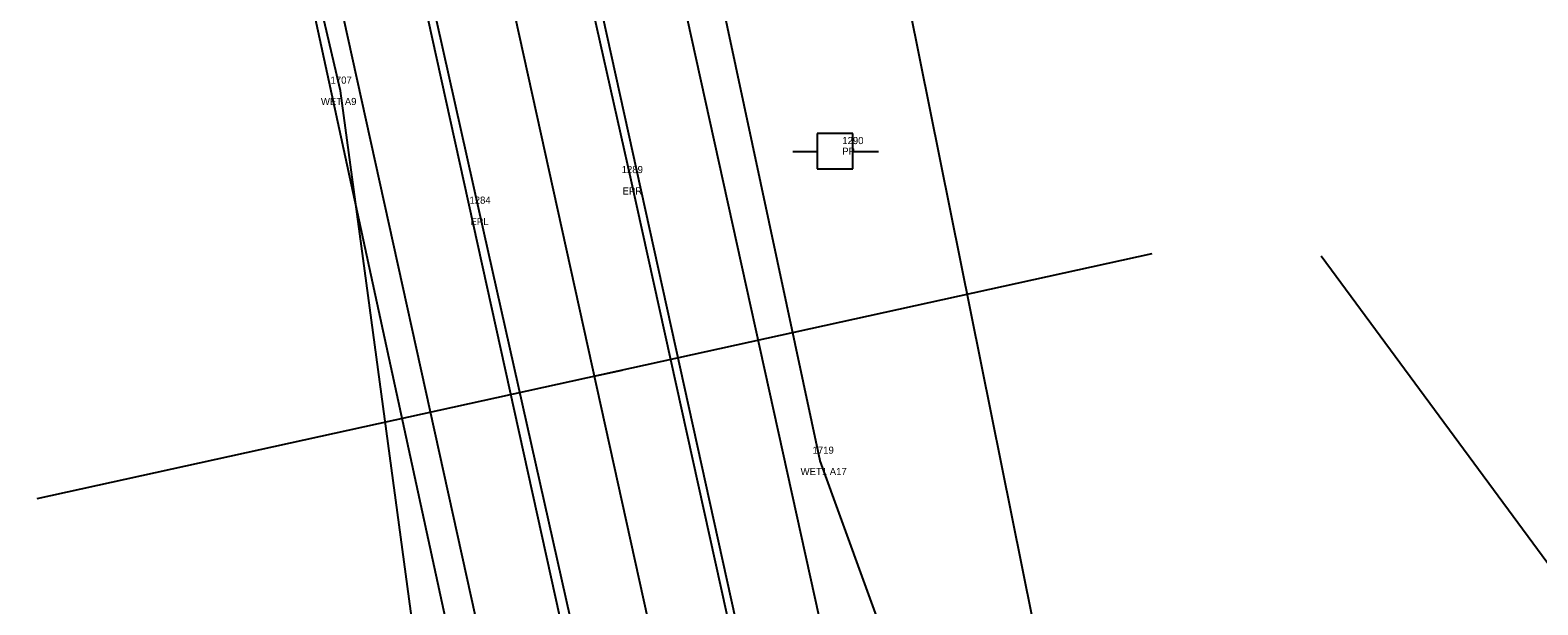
# Model space of a CAD drawing. Extents: x 2522090 to 2524658, y 882711 to 887512.
# Drawn here: x 2523667.1 to 2523878.4, y 885285.4 to 885366 of the extents above; entities that cross this region are included whole.
import ezdxf

# ---------------------------------------------------------------- set-up
doc = ezdxf.new("R2010")
doc.units = 0
for name, color, linetype in [('RD_EV_JurisArea', 7, 'Continuous'), ('RD_EX_H2O_WetLd_txCode', 7, 'Continuous'), ('RD_EX_Road', 7, 'Continuous'), ('RD_EX_Road_txCode', 7, 'Continuous'), ('RD_EX_UT', 7, 'Continuous'), ('RD_EX_UT_txCode', 7, 'Continuous'), ('RD_EX_VEG', 7, 'Continuous'), ('RD_HC_Cl', 7, 'Continuous'), ('RD_HC_Data_Tic', 7, 'Continuous'), ('RD_PD_Final_TrvlWay', 7, 'Continuous'), ('RD_PD_GR', 7, 'Continuous'), ('RD_PD_PatLn5', 7, 'Continuous'), ('RD_PD_PatLn6', 7, 'Continuous'), ('RD_SMD_Locator', 7, 'Continuous')]:
    doc.layers.add(name, color=color, linetype=linetype)

msp = doc.modelspace()

# ---------------------------------------------------------------- linework, layer by layer
at = {"layer": 'RD_EV_JurisArea'}
for points in [[(2523761.17, 885134.03), (2523740.58, 885149.03), (2523730.55, 885209.77), (2523710.6, 885357.47), (2523698.09, 885411.19), (2523674.93, 885498.62), (2523657.6, 885564.24), (2523640.82, 885610.87), (2523583.66, 885726.91), (2523539.21, 885693.17), (2523494.42, 885646.98)], [(2523761.17, 885134.03), (2523808.21, 885149.21), (2523821.91, 885178.64), (2523802.85, 885236.55), (2523777.81, 885305.56), (2523748.2, 885444.32), (2523730.68, 885516.88), (2523708.64, 885617.3), (2523698.71, 885662.02), (2523727.83, 885665.82), (2523757.3, 885671.75)]]:
    msp.add_lwpolyline(points, dxfattribs=at)
at = {"layer": 'RD_EX_Road'}
for p, q in [((2523751.35, 885344.92), (2523730.54, 885437.51)), ((2523730.02, 885340.63), (2523709.49, 885433.05)), ((2523771.24, 885254.79), (2523751.35, 885344.92)), ((2523750.32, 885250.18), (2523730.02, 885340.63))]:
    msp.add_line(p, q, dxfattribs=at)
at = {"layer": 'RD_EX_UT'}
for p, q in [((2523782.4, 885351.5), (2523777.4, 885351.5)), ((2523777.4, 885351.5), (2523777.4, 885346.5)), ((2523782.4, 885346.5), (2523782.4, 885351.5)), ((2523773.97, 885348.94), (2523777.44, 885348.94)), ((2523782.33, 885348.94), (2523785.97, 885348.94)), ((2523777.4, 885346.5), (2523782.4, 885346.5))]:
    msp.add_line(p, q, dxfattribs=at)
at = {"layer": 'RD_EX_VEG'}
for points in [[(2523825.62, 885207.01), (2523811.87, 885262.11), (2523733.02, 885654.22), (2523687.11, 885876.24)], [(2523749.81, 885158.06), (2523732.86, 885248.57), (2523691.62, 885438.95), (2523639.52, 885601.04)]]:
    msp.add_lwpolyline(points, dxfattribs=at)
at = {"layer": 'RD_HC_Cl'}
msp.add_line((2523641.17, 885794.2), (2524197.76, 883266.56), dxfattribs=at)
at = {"layer": 'RD_HC_Data_Tic'}
msp.add_line((2523746.15, 885317.42), (2523750.06, 885318.28), dxfattribs=at)
at = {"layer": 'RD_PD_Final_TrvlWay'}
for p, q in [((2523722.39, 885481.14), (2524037.44, 884050.42)), ((2523698.95, 885475.98), (2524014, 884045.26))]:
    msp.add_line(p, q, dxfattribs=at)
at = {"layer": 'RD_PD_GR'}
for p, q in [((2523722.6, 885533.67), (2523791.95, 885218.71)), ((2523746.05, 885208.61), (2523684.39, 885488.64))]:
    msp.add_line(p, q, dxfattribs=at)
at = {"layer": 'RD_PD_PatLn5'}
msp.add_line((2523824.28, 885334.62), (2523668.03, 885300.22), dxfattribs=at)
at = {"layer": 'RD_PD_PatLn6'}
msp.add_line((2523848.01, 885334.33), (2523942.89, 885205.5), dxfattribs=at)
at = {"layer": 'RD_SMD_Locator'}
for centre in [(2523710.6, 885357.47), (2523751.35, 885344.92), (2523730.02, 885340.63), (2523777.81, 885305.56)]:
    msp.add_circle(centre, 0.001, dxfattribs=at)

# ---------------------------------------------------------------- texts
at = {"layer": 'RD_EX_H2O_WetLd_txCode'}
for s, p in [('1707', (2523709.21, 885358.47)), ('WET A9', (2523707.86, 885355.47)), ('1719', (2523776.75, 885306.56)), ('WET1 A17', (2523775.07, 885303.56))]:
    msp.add_text(s, height=1, dxfattribs=at).set_placement(p)
at = {"layer": 'RD_EX_Road_txCode'}
for s, p in [('1289', (2523750, 885345.92)), ('EPR', (2523750.12, 885342.92)), ('1284', (2523728.67, 885341.63)), ('EPL', (2523728.81, 885338.63))]:
    msp.add_text(s, height=1, dxfattribs=at).set_placement(p)
at = {"layer": 'RD_EX_UT_txCode'}
for s, p in [('1290', (2523780.91, 885349.99)), ('PP', (2523780.91, 885348.49))]:
    msp.add_text(s, height=1, dxfattribs=at).set_placement(p)

doc.saveas('drawing.dxf')
